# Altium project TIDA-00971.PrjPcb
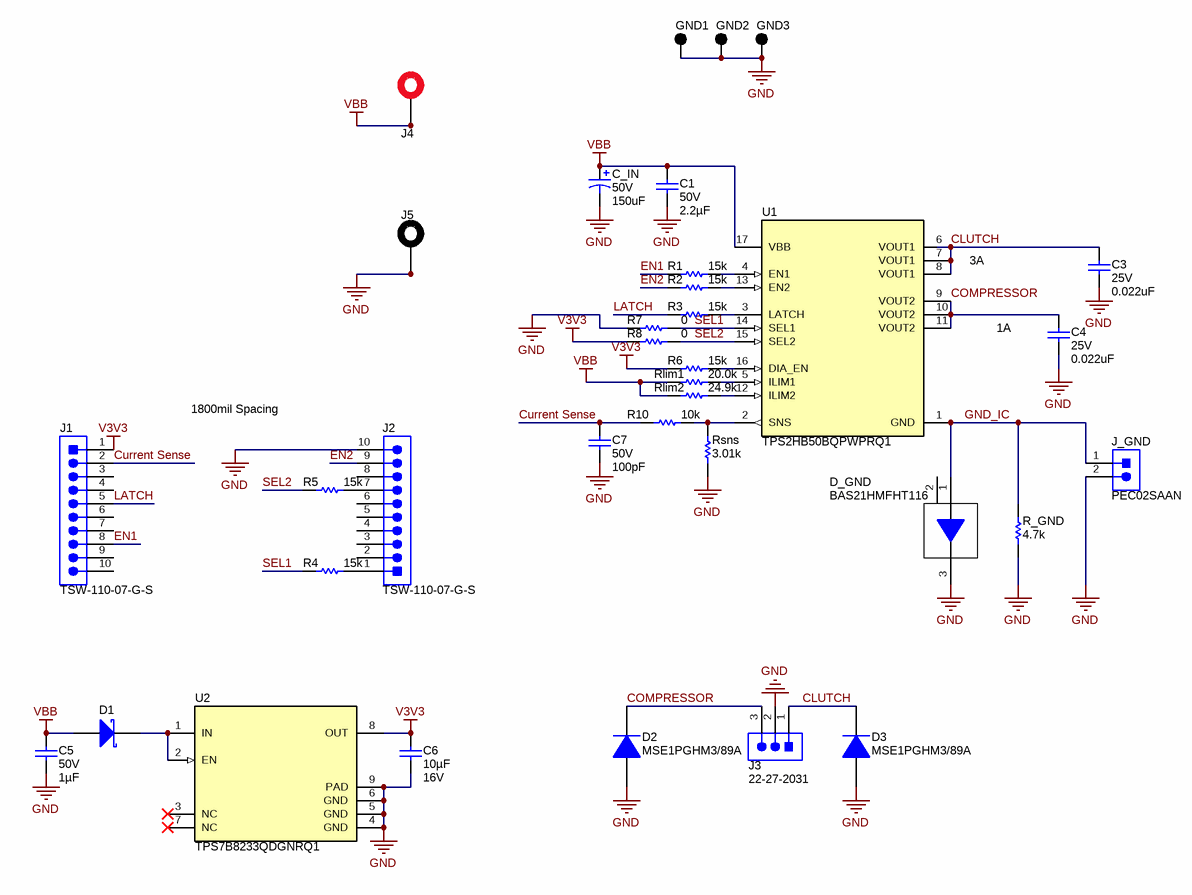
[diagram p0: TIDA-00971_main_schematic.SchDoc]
CopyrightYear: 2019; PCB_Layout: Cameron Phillips; PCB_Rev: E1; PRJ_Customer: Public Release; PRJ_Engineer: Cameron Phillips; PRJ_Number: TIDA-00971; PRJ_Title: Adjustable Current Limit for AC Compressor and Magnetic Clutch; SCH_Rev: E1; TechSupport: http://www.ti.com/support; TID: TIDA-00971
3 sheets, 43 parts. Net scope: global (net labels, ports and power ports of the same name join across sheets).
Board file: TIDA-00971_pcb.PcbDoc
Sheets:
  TIDA-00971_main_schematic.SchDoc
  EVM_Hardware.SchDoc
  CoverSheet.SchDoc

## Sheet TIDA-00971_main_schematic.SchDoc
size 431 x 279 mm; Date: Not shown in title block; ApprovedBy: Not shown in title block; CheckedBy: Not shown in title block; Author: Not shown in title block; CompanyName: Not shown in title block; Engineer: Not shown in title block; Organization: Not shown in title block; Address1: Not shown in title block; Address2: Not shown in title block; Address3: Not shown in title block; Address4: Not shown in title block; DocumentNumber: 2; Revision: Use project parameter SCH_Rev; SheetNumber: 2; SheetTotal: 3; PageSetup: Record=PageOptions¦CenterHorizontal=True¦CenterVertical=True¦PrintScale=1.00¦XCorrection=1.00¦YCorrection=1.00¦PrintKind=0¦BorderSize=5000000¦LeftOffset=0¦BottomOffset=0¦Orientation=2¦PaperLength=1000¦PaperWidth=1000¦Scale=100¦PaperSource=15¦PrintQuality=600¦MediaType=1¦DitherType=10¦PaperKind=Letter¦PrintScaleMode=1

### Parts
C1  VDC_V: 50V  ValueDisplayed: 2.2µF  [1206_180]  (hidden comment: C1206C225K5RACAUTO7210)
C3  VDC_V: 25V  ValueDisplayed: 0.022uF  [0603]  (hidden comment: C0603C223K3RACTU)
C4  VDC_V: 25V  ValueDisplayed: 0.022uF  [0603]  (hidden comment: C0603C223K3RACTU)
C5  VDC_V: 50V  ValueDisplayed: 1µF  [0805_HV]  (hidden comment: 08055C105K4Z2A)
C6  ValueDisplayed: 10µF  VDC_V: 16V  [0603]  (hidden comment: GRT188C81C106ME13D)
C7  VDC_V: 50V  ValueDisplayed: 100pF  [0402]  (hidden comment: CGA2B2C0G1H101J050BA)
C_IN  VDC_V: 50V  ValueDisplayed: 150uF  [SM_RADIAL_G]  (hidden comment: EEE-FK1H151P)
D1  ZLLS400QTA  [SOD-323]  (value not drawn)
D2  MSE1PGHM3/89A  [MicroSMP]
D3  MSE1PGHM3/89A  [MicroSMP]
D_GND  BAS21HMFHT116  [SOT-23]
GND1  5011  [Keystone5011]  (value not drawn)
GND2  5011  [Keystone5011]  (value not drawn)
GND3  5011  [Keystone5011]  (value not drawn)
J1  TSW-110-07-G-S  [TSW-110-07-G-S]
J2  TSW-110-07-G-S  [TSW-110-07-G-S]
J3  22-27-2031  [MOLEX_22-27-2031]
J4  571-0500  [571-0500]  (value not drawn)
J5  571-0100  [571-0100]  (value not drawn)
J_GND  PEC02SAAN  [CONN_PEC02SAAN]
R1  ValueDisplayed: 15k  [0402]  (hidden comment: CRCW040215K0JNED)
R2  ValueDisplayed: 15k  [0402]  (hidden comment: CRCW040215K0JNED)
R3  ValueDisplayed: 15k  [0402]  (hidden comment: CRCW040215K0JNED)
R4  ValueDisplayed: 15k  [0402]  (hidden comment: CRCW040215K0JNED)
R5  ValueDisplayed: 15k  [0402]  (hidden comment: CRCW040215K0JNED)
R6  ValueDisplayed: 15k  [0402]  (hidden comment: CRCW040215K0JNED)
R7  ValueDisplayed: 0  [0402]  (hidden comment: ERJ-2GE0R00X)
R8  ValueDisplayed: 0  [0402]  (hidden comment: ERJ-2GE0R00X)
R10  ValueDisplayed: 10k  [0402]  (hidden comment: CRCW040210K0JNED)
R_GND  ValueDisplayed: 4.7k  [0603]  (hidden comment: RC0603JR-074K7L)
Rlim1  ValueDisplayed: 20.0k  [0402]  (hidden comment: CRCW040220K0FKED)
Rlim2  ValueDisplayed: 24.9k  [0402]  (hidden comment: CRCW040224K9FKED)
Rsns  ValueDisplayed: 3.01k  [0603]  (hidden comment: CRCW06033K01FKEA)
U1  TPS2HB50BQPWPRQ1  [TPS1HA08-Q1_L]
U2  TPS7B8233QDGNRQ1  [DGN0008D_N]

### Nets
GND: C1.2 C3.2 C4.2 C5.2 C6.2 C7.2 C_IN.2(-) D2.2(A) D3.2(A) D_GND.3(C) GND1.1 GND2.1 GND3.1 J2.10 J3.2 J5.1 J5.2 J_GND.2 R7.1 R_GND.1 Rsns.1 U2.4(GND) U2.5(GND) U2.6(GND) U2.9(PAD)
V3V3: C6.1 J1.1 R6.1 R8.1 U2.8(OUT)
VBB: C1.1 C5.1 C_IN.1(+) D1.2(A) J4.1 J4.2 Rlim1.1 Rlim2.1 U1.17(VBB)
CLUTCH: C3.1 D3.1(K) J3.1 U1.6(VOUT1) U1.7(VOUT1) U1.8(VOUT1)
COMPRESSOR: C4.1 D2.1(K) J3.3 U1.9(VOUT2) U1.10(VOUT2) U1.11(VOUT2)
Current Sense: C7.1 J1.2 R10.1
EN1: J1.8 R1.1
EN2: J2.9 R2.1
GND_IC: D_GND.1(A) J_GND.1 R_GND.2 U1.1(GND)
LATCH: J1.5 R3.1
SEL1: R4.1 R7.2 U1.14(SEL1)
SEL2: R5.1 R8.2 U1.15(SEL2)
NetD1_1: D1.1(K) U2.1(IN) U2.2(EN)
NetJ2_1: J2.1 R4.2
NetJ2_7: J2.7 R5.2
NetR1_2: R1.2 U1.4(EN1)
NetR2_2: R2.2 U1.13(EN2)
NetR3_2: R3.2 U1.3(LATCH)
NetR6_2: R6.2 U1.16(DIA_EN)
NetR10_2: R10.2 Rsns.2 U1.2(SNS)
NetRlim1_2: Rlim1.2 U1.5(ILIM1)
NetRlim2_2: Rlim2.2 U1.12(ILIM2)

Not connected (* = marked no-connect by the designer): D_GND 2(NC); J1 3 4 6 7 9 10; J2 2 3 4 5 6 8; U2 3(NC)* 7(NC)*

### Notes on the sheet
- (near U1) 3A
- 1A
- 1800mil Spacing

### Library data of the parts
C1 = CMP-0080745-1: CAP, CERM, 2.2 µF, 50 V,+/- 10%, X7R, AEC-Q200 Grade 1, 1206; Manufacturer: KEMET; SizeAreaWB_mm2: 10.92; SizeArea_mm2: 5.12; AEC Qualified: Y; AEC Category: Q200; Value: 2.2uF; TaMax_C: 125°C; SizeZ_mm: 1.8; AEC Grade: 1; Polarized: N; TaMin_C: -55°C; SizeY_mm: 1.6; U/M: EA; CompType: Capacitor; SizeX_mm: 3.2; Cap_Case: 1206
C3 C4 = CMP-0006899-4: CAP, CERM, 0.022 uF, 25 V, +/- 10%, X7R, 0603; Manufacturer: Kemet; TaMin_C: -55°C; Polarized: N; SizeAreaWB_mm2: 4.68; Value1: Unknown; U/M: EA; TaMax_C: 125°C; SizeZ_mm: 1; SizeX_mm: 1.6; SizeY_mm: 0.8; SizeArea_mm2: 1.28; Cap_F: 22nF; AEC Category: Q200
C5 = CMP-0083705-1: CAP, CERM, 1 µF, 50 V,+/- 10%, X7R, AEC-Q200 Grade 1, 0805; Manufacturer: AVX; SizeAreaWB_mm2: 6.75; SizeArea_mm2: 2.5; AEC Qualified: Y; AEC Category: Q200; Value: 1uF; TaMax_C: 125°C; SizeZ_mm: 1.45; AEC Grade: 1; Polarized: N; TaMin_C: -55°C; SizeY_mm: 1.25; U/M: EA; SizeX_mm: 2; Cap_Case: 0805
C6 = CMP-0085644-1: CAP, CERM, 10 µF, 16 V,+/- 20%, X6S, AEC-Q200 Grade 2, 0603; Manufacturer: MuRata; TaMin_C: -55°C; SizeY_mm: 0.8; SizeX_mm: 1.6; SizeZ_mm: 1; SizeArea_mm2: 1.28; Value: 10uF; AEC Grade: 2; Polarized: N; U/M: EA; TaMax_C: 105°C; AEC Qualified: Y; AEC Category: Q200; SizeAreaWB_mm2: 4.68
C7 = CMP-0006308-2: CAP, CERM, 100 pF, 50 V, +/- 5%, C0G/NP0, AEC-Q200 Grade 1, 0402; Manufacturer: TDK; TaMin_C: -55°C; Polarized: N; SizeAreaWB_mm2: 3; Value1: Unknown; U/M: EA; Value: 100pF; TaMax_C: 125°C; SizeZ_mm: 0.6; SizeX_mm: 1; SizeY_mm: 0.5; AEC Qualified: Y; AEC Category: Q200
C_IN = CMP-0011178-2: CAP, AL, 150 uF, 50 V, +/- 20%, 0.18 ohm, AEC-Q200 Grade 2, SMD; Manufacturer: Panasonic; TaMin_C: -55°C; ESR_ohm: 1.8d; Polarized: Y; SizeAreaWB_mm2: 172.2; U/M: EA; Value: 150uF; TaMax_C: 105°C; SizeZ_mm: 10.2; SizeX_mm: 12; SizeY_mm: 10.3; Cap_Case: G; SizeArea_mm2: 123.6; CompType: Capacitor; Cap_F: 150µF; IRMS_A: 6.7dA; AEC Grade: 2; AEC Category: Q200
D1 = CMP-0028792-2: Diode, Schottky, 40 V, 0.52 A, AEC-Q101, SOD-323; Manufacturer: Diodes Inc.; Value: 40V; SizeZ_mm: 1; Io_A: 5.2dA; SizeAreaWB_mm2: 8.695; SizeArea_mm2: 3.645; TJmax_C: 150°C; Green_REACh: Incomplete; SizeX_mm: 2.7; AEC Category: Q101; Value1: 0.52A; SizeY_mm: 1.35; AEC Qualified: Y; Green_Lifecycle: Not Set
D2 D3 = CMP-0029173-2: Diode, Standard Recovery Rectifier, 400 V, 1 A, AEC-Q101, MicroSMP; Manufacturer: Vishay-Semiconductor; Io_A: 1A; Value2: 1.1V; AEC Qualified: Y; SizeZ_mm: 0.73; Vr_V: 600V; Value: 400V; SizeArea_mm2: 3.25; RJC_CperW: 40; Green_REACh: Incomplete; SizeAreaWB_mm2: 8.05; TJmax_C: 175°C; Green_Lifecycle: Not Set; SizeY_mm: 1.3; AEC Category: Q101; SizeX_mm: 2.5
D_GND = CMP-0080708-2: Diode, Switching, 200 V, 0.2 A, AEC-Q101, SOT-23; Manufacturer: Rohm; SizeY_mm: 3; TJmax_C: 150°C; SizeAreaWB_mm2: 14; AEC Category: Q101; Value1: 0.2A; Value: 200V; SizeZ_mm: 1.1; AEC Qualified: Y; SizeX_mm: 2.5; SizeArea_mm2: 7.5; Value2: 1.25V; Io_A: 2dA
GND1-GND3 = CMP-0055148-1: Test Point, Multipurpose, Black, TH; Manufacturer: Keystone; CNHeader: FALSE; Green_Lifecycle: Active; Green_REACh: Passed; ContactFinish: Silver; CT: TRUE
J1 J2 = CMP-0075422-1: Header, 100mil, 10x1, Gold, TH; Manufacturer: Samtec; Pitch_mm: 2.54; Cert_VDE: N; Gender: Male; Cert_CSA: Y; Voltage_V: 550V; Green_REACh: Passed; Current_A: 6.3A; CT: False; Green_Lifecycle: Active; Row_Count: 1; CNHeader: True
J3 = CMP-0055191-1: CONN HEADER 3POS .100 VERT TIN; Manufacturer: Molex; CNHeader: FALSE; Green_Lifecycle: Active; Green_REACh: Passed
J4 = CMP-0055393-3: Standard Banana Jack, insulated, 10A, red; Manufacturer: DEM Manufacturing; Green_REACh: Incomplete; Green_Lifecycle: Not Set
J5 = CMP-0055389-3: Standard Banana Jack, insulated, 10A, black; Manufacturer: DEM Manufacturing; Green_REACh: Incomplete; Green_Lifecycle: Not Set
J_GND = CMP-0002337-1: Header, 100mil, 2x1, Tin, TH; Manufacturer: Sullins Connector Solutions; CNHeader: TRUE; Current_A: 3A; Green_Lifecycle: Not Set; Shrouded: N; Gender: Male; Green_REACh: Incomplete; Voltage_V: 1.8kV; Row_Count: 1; Pitch_mm: 2.54; CT: FALSE; Cert_UL: Y
R1-R6 = CMP-0026842-3: RES, 15 k, 5%, 0.063 W, AEC-Q200 Grade 0, 0402; Manufacturer: Vishay-Dale; Power_W: 63mW; TempCo: 200 ppm/C; Value_Code: 15k0; Value: 15k; EIA_Code: E24; SizeX_mm: 1; SizeY_mm: 0.5; SizeZ_mm: 0.6; Value2: 0.063W; AEC Qualified: Y; VDC_V: 50V; AEC Category: Q200; AEC Grade: 0
R7 R8 = CMP-0026992-3: RES, 0, 5%, 0.1 W, AEC-Q200 Grade 0, 0402; Manufacturer: Panasonic; Power_W: 100mW; TempCo: 600 ppm/C; Value_Code: 0000; Value: 0; EIA_Code: E24; SizeX_mm: 1; SizeY_mm: 0.5; SizeZ_mm: 0.6; Value2: 0.1W; AEC Qualified: Y; VDC_V: 50V; AEC Category: Q200; SizeAreaWB_mm2: 3
R10 = CMP-0026825-5: RES, 10 k, 5%, 0.063 W, AEC-Q200 Grade 0, 0402; Manufacturer: Vishay-Dale; Power_W: 63mW; TempCo: 200 ppm/C; Value_Code: 10k0; Value: 10k; EIA_Code: E24; SizeX_mm: 1; SizeY_mm: 0.5; SizeZ_mm: 0.6; Value2: 0.063W; AEC Qualified: Y; VDC_V: 50V; AEC Category: Q200; AEC Grade: 0
R_GND = CMP-0025927-5: RES, 4.7 k, 5%, 0.1 W, 0603; Manufacturer: Yageo; Power_W: 100mW; TempCo: 100 ppm/C; Value_Code: 4k70; Value: 4.7k; EIA_Code: E24; SizeX_mm: 1.6; SizeY_mm: 0.8; SizeZ_mm: 1; Value2: 0.1W; SizeArea_mm2: 1.28; AEC Qualified: N; VDC_V: 75V; AEC Category: Q200; SizeAreaWB_mm2: 4.68
Rlim1 = CMP-0026162-2: RES, 20.0 k, 1%, 0.063 W, AEC-Q200 Grade 0, 0402; Manufacturer: Vishay-Dale; Power_W: 63mW; TempCo: 100 ppm/C; Value_Code: 20k0; Value: 20.0k; EIA_Code: E96; Res_ohm: 20k; SizeX_mm: 1; SizeY_mm: 0.5; SizeZ_mm: 0.6; Value2: 0.063W; AEC Qualified: Y; VDC_V: 50V; AEC Category: Q200; AEC Grade: 0
Rlim2 = CMP-0026196-2: RES, 24.9 k, 1%, 0.063 W, AEC-Q200 Grade 0, 0402; Manufacturer: Vishay-Dale; Power_W: 63mW; TempCo: 100 ppm/C; Value_Code: 24k9; Value: 24.9k; EIA_Code: E96; SizeX_mm: 1; SizeY_mm: 0.5; SizeZ_mm: 0.6; Value2: 0.063W; AEC Qualified: Y; VDC_V: 50V; AEC Category: Q200; AEC Grade: 0
Rsns = CMP-0022371-4: RES, 3.01 k, 1%, 0.1 W, AEC-Q200 Grade 0, 0603; Manufacturer: Vishay-Dale; Power_W: 100mW; TempCo: 100 ppm/C; Value_Code: 3k01; Value: 3.01k; EIA_Code: E96; SizeX_mm: 1.6; SizeY_mm: 0.8; SizeZ_mm: 1; Value2: 0.1W; SizeArea_mm2: 1.28; AEC Qualified: Y; VDC_V: 75V; AEC Category: Q200; AEC Grade: 0
U1 = CMP-0076732-1: 40-V, 50-mOhm Dual-Channel Smart High-Side Switch, TPS2HB50-Q1 (TSSOP-16); Alternate Manufacturer: Texas Instruments; SizeX_mm: 6.4; CompType: IC; SizeAreaWB_mm2: 58.8; SizeZ_mm: 1.2; SizeY_mm: 5.0; U/M: EA; SizeArea_mm2: 32.0
U2 = CMP-0013312-4: 300mA High-Voltage Ultra-Low-Iq Low-Dropout (LDO) Regulator, DGN0008D (VSSOP-8); Manufacturer: Texas Instruments; SizeX_mm: 5.05; SizeY_mm: 3.1; CompType: IC; SizeZ_mm: 1.1; SizeArea_mm2: 15.655; SizeAreaWB_mm2: 35.955; AEC Category: Q200; AEC Qualified: Y

## Sheet EVM_Hardware.SchDoc
size 431 x 279 mm; Date: Not shown in title block; ApprovedBy: Not shown in title block; CheckedBy: Not shown in title block; Author: Not shown in title block; CompanyName: Not shown in title block; Engineer: Not shown in title block; Organization: Not shown in title block; Address1: Not shown in title block; Address2: Not shown in title block; Address3: Not shown in title block; Address4: Not shown in title block; DocumentNumber: 3; Revision: Use project parameter SCH_Rev; SheetNumber: 3; SheetTotal: 3; PageSetup: Record=PageOptions¦CenterHorizontal=True¦CenterVertical=True¦PrintScale=1.00¦XCorrection=1.00¦YCorrection=1.00¦PrintKind=0¦BorderSize=5000000¦LeftOffset=0¦BottomOffset=0¦Orientation=2¦PaperLength=1000¦PaperWidth=1000¦Scale=100¦PaperSource=15¦PrintQuality=600¦MediaType=1¦DitherType=10¦PaperKind=Letter¦PrintScaleMode=1
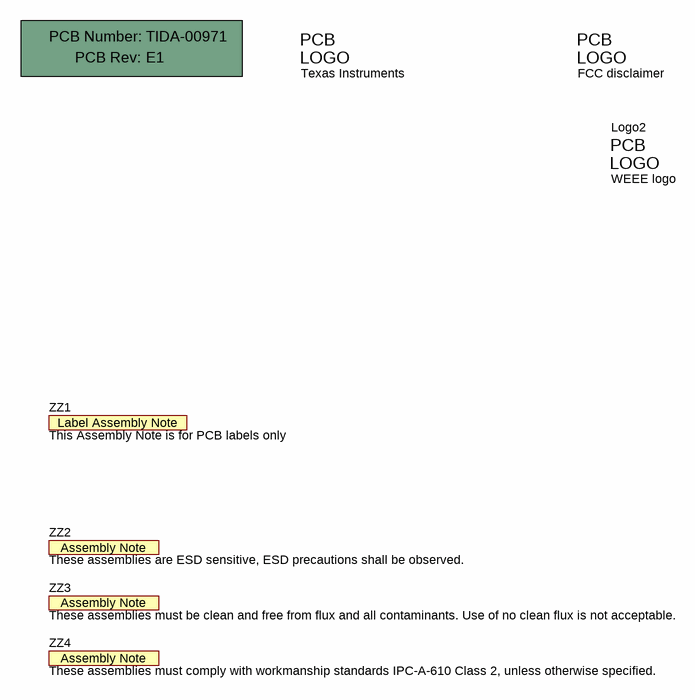
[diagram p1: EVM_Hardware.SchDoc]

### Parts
!PCB  Printed Circuit Board  (value not drawn)  (mechanical)
Logo1  Texas Instruments  [TI_Stacked_Overlay_Small]  (no BOM)
Logo2  WEEE logo  [WEEE_Minimum]  (no BOM)
Logo3  FCC disclaimer  [FCC_disclaimer]  (no BOM)
ZZ1  This Assembly Note is for PCB labels only  [AssemblyNoteLabel]  (no BOM)
ZZ2  These assemblies are ESD sensitive, ESD precautions shall be observed.  [AssemblyNote]  (no BOM)
ZZ3  These assemblies must be clean and free from flux and all contaminants. Use of no clean flux is not acceptable.  [AssemblyNote]  (no BOM)
ZZ4  These assemblies must comply with workmanship standards IPC-A-610 Class 2, unless otherwise specified.  [AssemblyNote]  (no BOM)

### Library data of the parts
!PCB = CMP-0003618-2: Manufacturer: Any; PartNumber: TIDA-00971
Logo1 = CMP-0074838-1: Texas Instrument Corporate Signature; SymbolCreator: a0412235; Lib Reference: TI_Logo; Library Reference: Logo
Logo2 = CMP-0074769-1
Logo3 = CMP-0074847-1: FCC_disclaimer; Library Reference: Logo
ZZ1 = CMP-0003616-3
ZZ2 = CMP-0077236-1
ZZ3 = CMP-0077237-1
ZZ4 = CMP-0077238-1

## Sheet CoverSheet.SchDoc
size 431 x 279 mm; Date: Not shown in title block; ApprovedBy: Not shown in title block; CheckedBy: Not shown in title block; Author: Not shown in title block; CompanyName: Not shown in title block; Engineer: Not shown in title block; Organization: Not shown in title block; Address1: Not shown in title block; Address2: Not shown in title block; Address3: Not shown in title block; Address4: Not shown in title block; DocumentNumber: 1; Revision: Use project parameter SCH_Rev; SheetNumber: 1; SheetTotal: 3; PageSetup: Record=PageOptions¦CenterHorizontal=True¦CenterVertical=True¦PrintScale=1.00¦XCorrection=1.00¦YCorrection=1.00¦PrintKind=0¦BorderSize=5000000¦LeftOffset=0¦BottomOffset=0¦Orientation=2¦PaperLength=1000¦PaperWidth=1000¦Scale=100¦PaperSource=15¦PrintQuality=600¦MediaType=1¦DitherType=10¦PaperKind=Letter¦PrintScaleMode=1
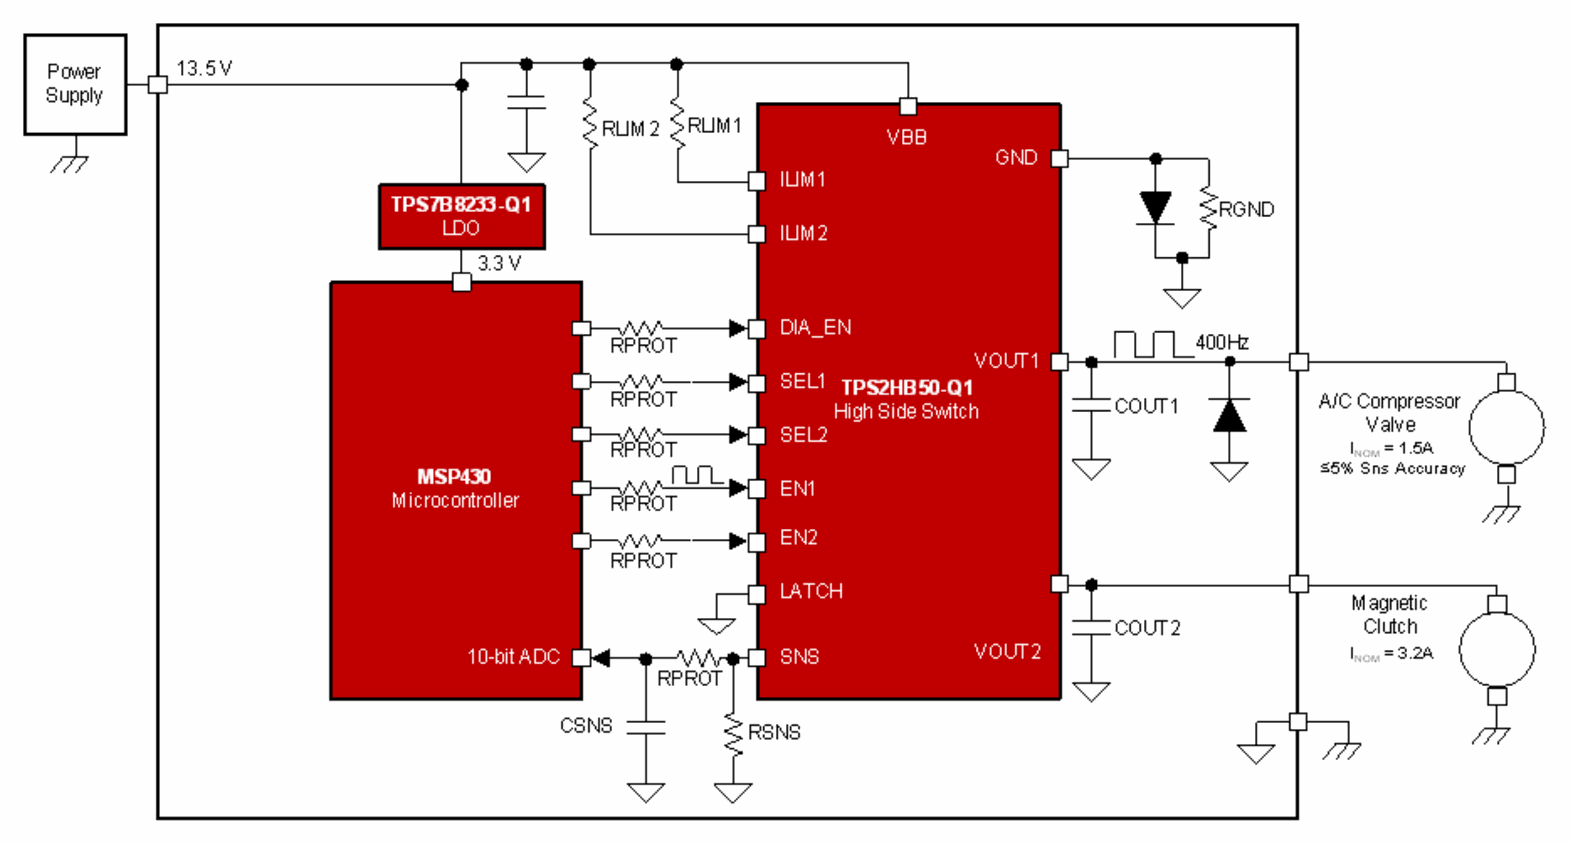
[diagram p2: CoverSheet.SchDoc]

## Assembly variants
001: not fitted C_IN R4 R5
